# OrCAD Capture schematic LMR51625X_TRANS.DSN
size D
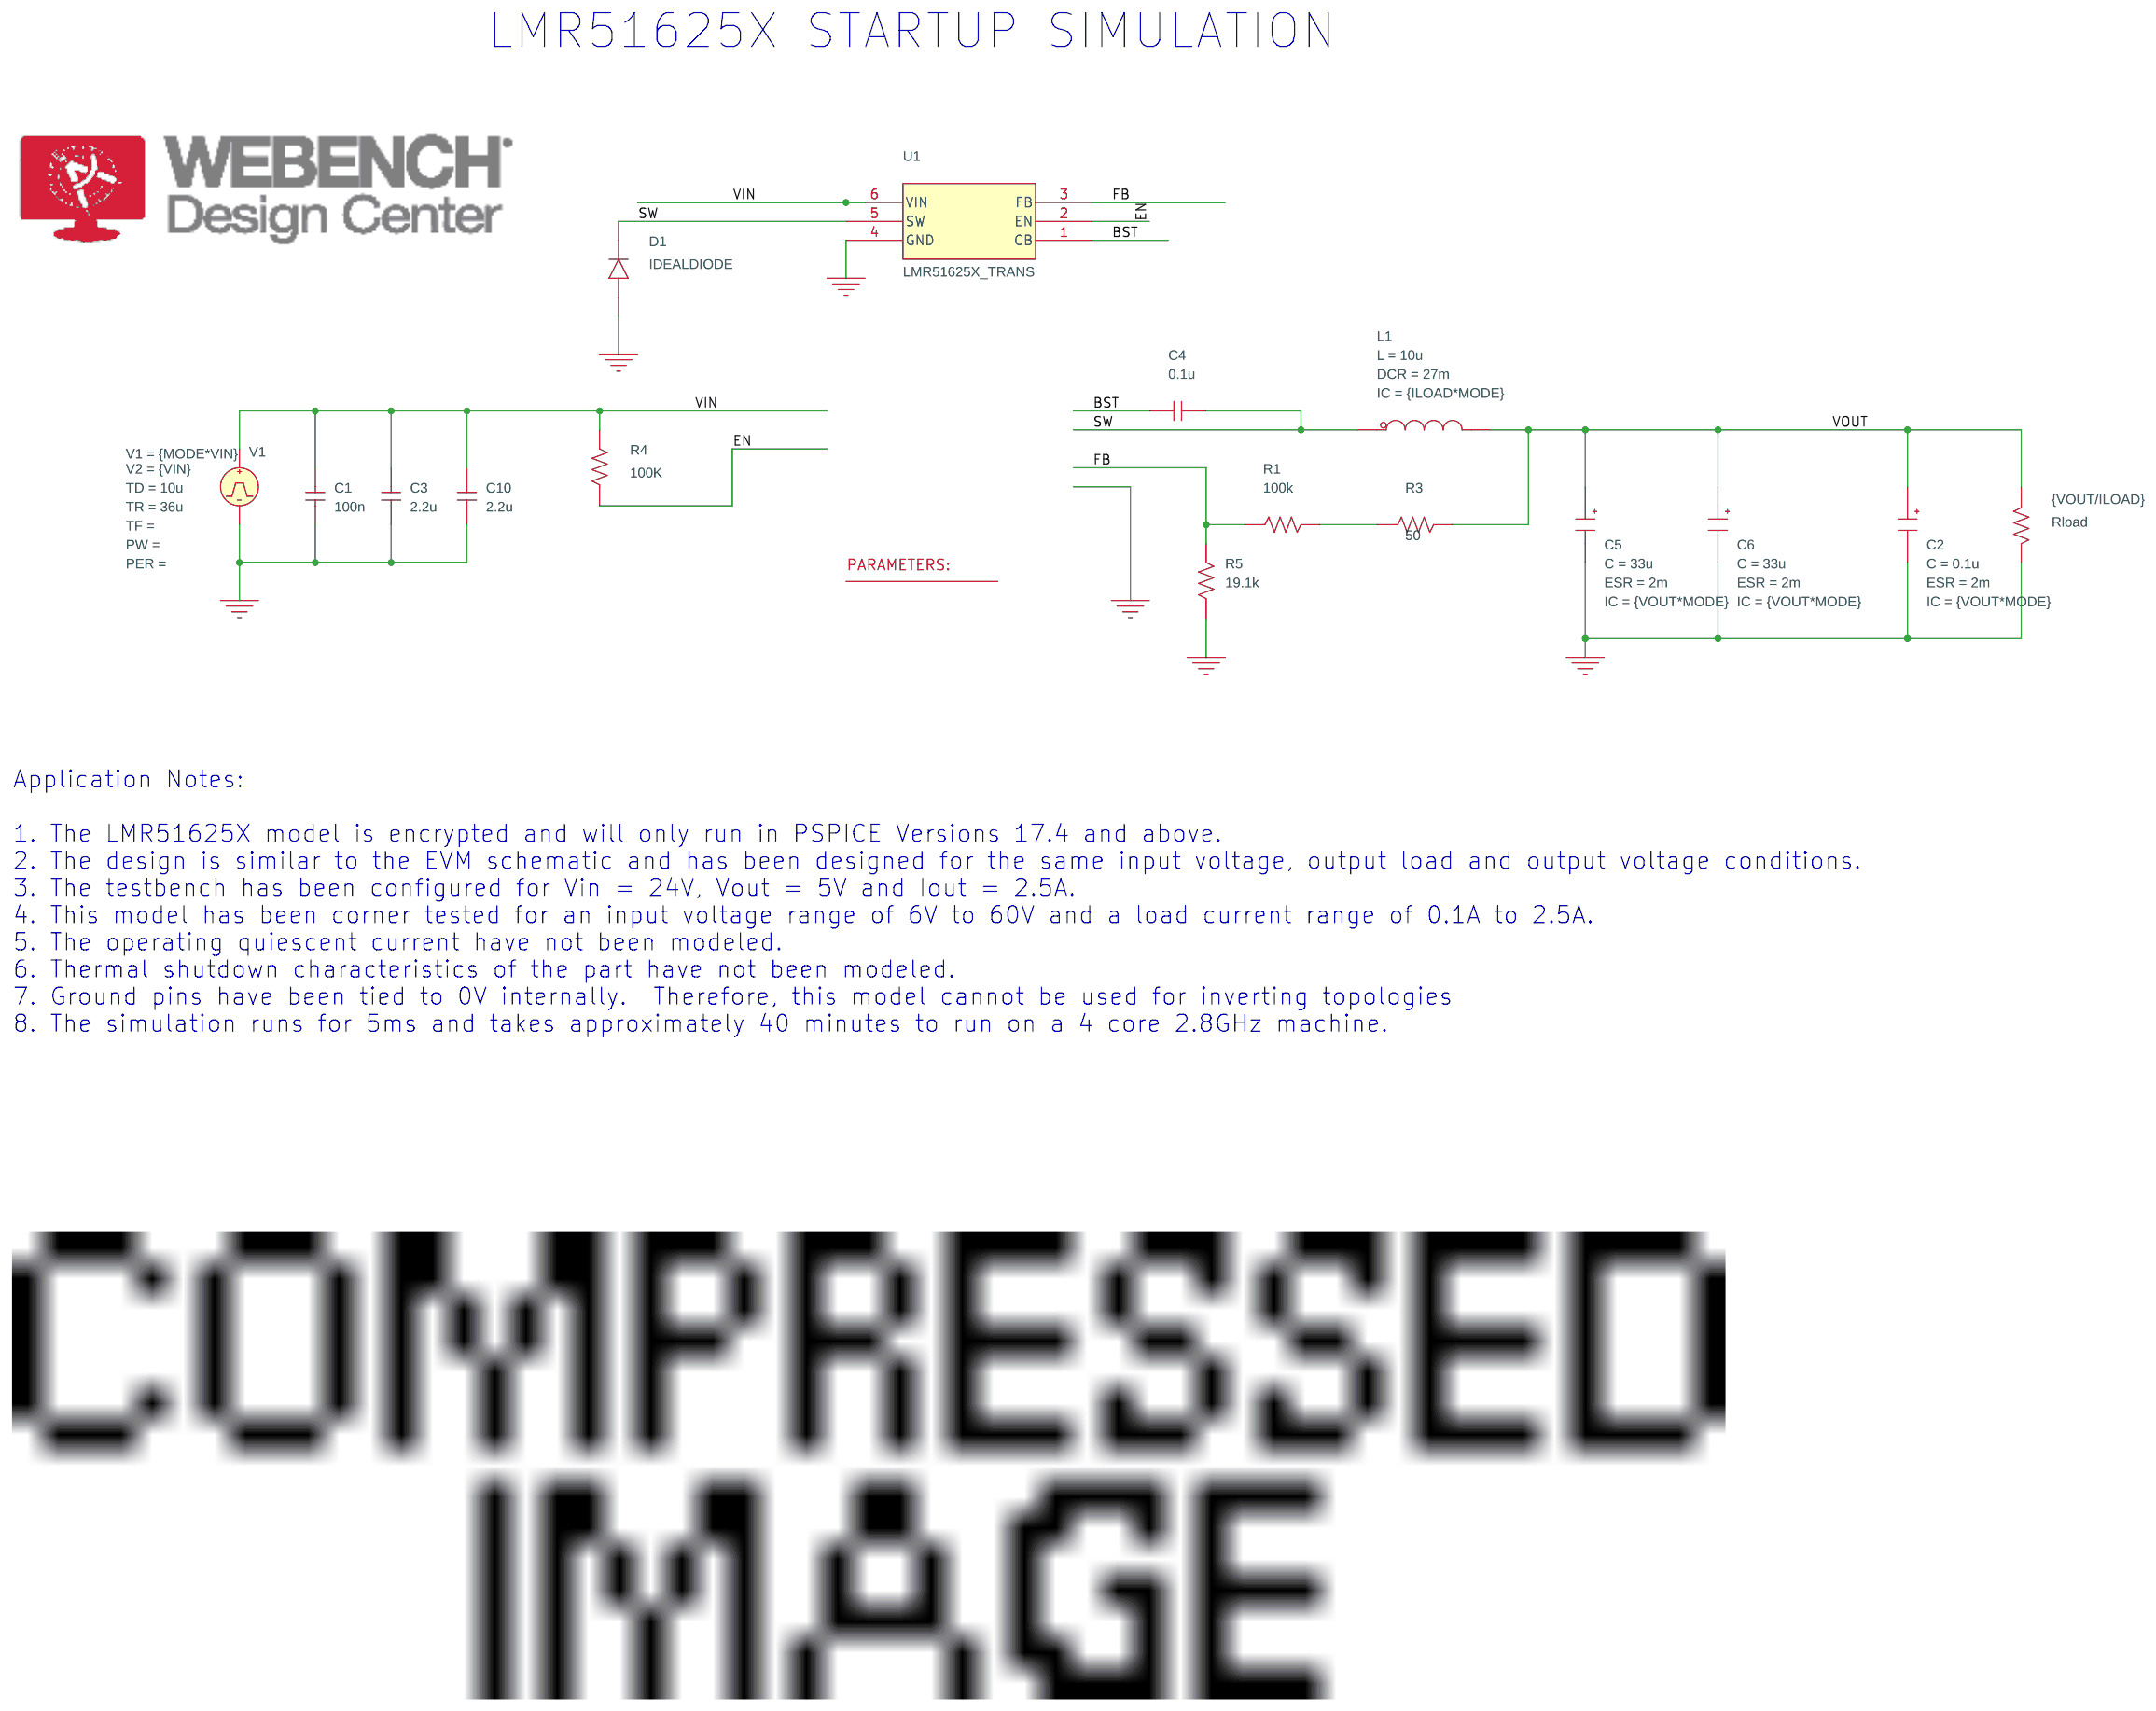
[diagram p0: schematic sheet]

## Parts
1  PARAM
C1  100n  [RAD/CK05]
C2  CESR
C3  2.2u  [RAD/CK05]
C4  0.1u  [RAD/CK05]
C5  CESR
C6  CESR
C10  2.2u  [RAD/CK05]
D1  IDEALDIODE  [DI]
L1  LDCR
R1  100k  [RC05]
R3  50  [AX/RC05]
R4  100K  [AX/RC05]
R5  19.1k  [RC05]
Rload  {VOUT/ILOAD}  [AX/RC05]
U1  LMR51625X_TRANS
V1  VPULSE

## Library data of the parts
1 = PARAM: ILOAD: 2.5; VIN: 24; VOUT: 5
C1 C3 C10 = C
C2 = CESR_0: C: 0.1u; ESR: 2m; IC: {VOUT*MODE}; PSpiceTemplate: X^@REFDES %IN %OUT @MODEL PARAMS:  ?C|C=@C||C=100u|  ?ESR|ESR=@ESR||ESR=0.01| ?X|X=@X||X=2|  ?IC|IC=@IC||IC=2|; X: 1
C4 = C: IC: -3.3
C5 C6 = CESR_0: C: 33u; ESR: 2m; IC: {VOUT*MODE}; PSpiceTemplate: X^@REFDES %IN %OUT @MODEL PARAMS:  ?C|C=@C||C=100u|  ?ESR|ESR=@ESR||ESR=0.01| ?X|X=@X||X=2|  ?IC|IC=@IC||IC=2|; X: 1
D1 = IDEALDIODE
L1 = LDCR_0: DCR: 27m; IC: {ILOAD*MODE}; L: 10u; PSpiceTemplate: X^@REFDES %IN %OUT @MODEL PARAMS:  ?L|L=@L||L=1u|  ?DCR|DCR=@DCR||DCR=0.01| ?IC|IC=@IC||IC=0|
R1 R3-R5 Rload = R
U1 = LMR51625X_TRANS
V1 = VPULSE: TD: 10u; TR: 36u; V1: {MODE*VIN}; V2: {VIN}

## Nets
VIN: C1.2 C3.2 C10.2 R4.2 U1.6(VIN) V1.1(+)
0: C1.1 C2.3(OUT) C3.1 C5.3(OUT) C6.3(OUT) C10.1 D1.2(AN) R5.1 Rload.2 U1.4(GND) V1.2(-)
BST: C4.1 U1.1(CB)
EN: R4.1 U1.2(EN)
FB: R1.1 R5.2 U1.3(FB)
SW: C4.2 D1.1(CAT) L1.1(IN) U1.5(SW)
VOUT: C2.1(IN) C5.1(IN) C6.1(IN) L1.3(OUT) R3.2 Rload.1
N16776855: R1.2 R3.1

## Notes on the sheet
- LMR51625X STARTUP SIMULATION
- Application Notes:
  1. The LMR51625X model is encrypted and will only run in PSPICE Versions 17.4 and above.
  2. The design is similar to the EVM schematic and has been designed for the same input voltage, output load and output voltage conditions.
  3. The testbench has been configured for Vin = 24V, Vout = 5V and Iout = 2.5A.
  4. This model has been corner tested for an input voltage range of 6V to 60V and a load current range of 0.1A to 2.5A.
  5. The operating quiescent current have not been modeled.
  6. Thermal shutdown characteristics of the part have not been modeled.
  7. Ground pins have been tied to 0V internally.  Therefore, this model cannot be used for inverting topologies
  8. The simulation runs for 5ms and takes approximately 40 minutes to run on a 4 core 2.8GHz machine.
